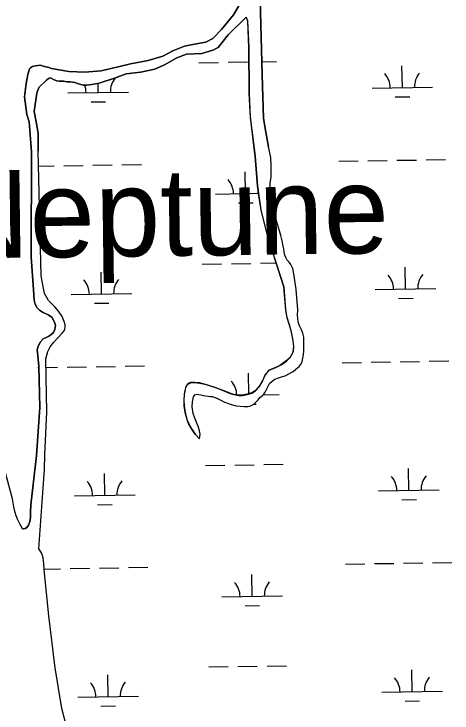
# Model space of a CAD drawing. Extents: x 3855477 to 3893699, y 299188 to 325115.
# Drawn here: x 3861611 to 3862334, y 317862 to 319017 of the extents above; entities that cross this region are included whole.
import ezdxf

# ---------------------------------------------------------------- set-up
doc = ezdxf.new("R2010")
doc.units = 0
for name, color, linetype in [('V-RIVR-EDGE', 7, 'Continuous'), ('V-TOPO-GNAM-IDEN', 7, 'Continuous'), ('V-TOPO-SHOR', 7, 'Continuous'), ('V-WETL-SWMP', 7, 'Continuous')]:
    doc.layers.add(name, color=color, linetype=linetype)

msp = doc.modelspace()

# ---------------------------------------------------------------- linework, layer by layer
at = {"layer": 'V-RIVR-EDGE'}
msp.add_spline([(3859519.3, 318133.3), (3859529.1, 318128.1), (3859557.8, 318117.3), (3859589.2, 318096.9), (3859608.3, 318091.7), (3859632.6, 318087.2), (3859655.7, 318083.2), (3859677.6, 318079.1), (3859695.1, 318076.3), (3859736.6, 318066.2), (3859764.5, 318061.4), (3859790.3, 318051.8), (3859824.2, 318038.5), (3859868.4, 318020.1), (3859890.7, 318012), (3859919.3, 318000.8), (3859946.4, 317985.2), (3859972.3, 317972.4), (3859987.4, 317966), (3859998.9, 317963.2), (3860007.3, 317958.4), (3860026.8, 317947.5), (3860045.9, 317937.5), (3860071.4, 317923.9), (3860094.9, 317913.9), (3860108.4, 317909.5), (3860130.3, 317897.1), (3860149.8, 317885.5), (3860170.5, 317876.3), (3860195.2, 317867.8), (3860221.1, 317854.2), (3860250.5, 317837.4), (3860275.2, 317822.6), (3860303, 317809.4), (3860359.6, 317779.3), (3860406.5, 317758.5), (3860436.8, 317744.1), (3860477.8, 317728.8), (3860496.5, 317723.6), (3860519.2, 317713.2), (3860555.8, 317696), (3860594.8, 317675.5), (3860632.3, 317656.3), (3860676.4, 317633.1), (3860726.6, 317605.5), (3860768, 317581.1), (3860790.7, 317570.6), (3860877.8, 317518.6), (3860907.7, 317504.6), (3860923.6, 317499.8), (3860947.5, 317491.7), (3860980.9, 317479.3), (3861011.2, 317471.3), (3861035.1, 317464.4), (3861065.4, 317456), (3861094, 317449.1), (3861112.8, 317445.1), (3861139.1, 317440.3), (3861167.3, 317430.2), (3861205.2, 317422.2), (3861236.2, 317418.9), (3861259.4, 317418), (3861273.7, 317417.2), (3861300, 317410), (3861325.9, 317397.5), (3861341.8, 317391.5), (3861353.7, 317387.9), (3861368.5, 317388.7), (3861377.7, 317388.7), (3861664.7, 317282.7), (3861681.1, 317276.7), (3861681.1, 317274.3), (3861687, 317270.7), (3861700.2, 317265.1), (3861705.7, 317256.7), (3861715.7, 317246.3), (3861721.2, 317241.5), (3861723.2, 317234.4), (3861726.4, 317227.6), (3861750.6, 317208), (3861757.4, 317197.6), (3861762.5, 317188.8), (3861767.3, 317187.2), (3861780.1, 317185.6), (3861788, 317178), (3861803.1, 317165.2), (3861810.3, 317151.6), (3861809.8, 317139.7), (3861814.2, 317132.9), (3861819.8, 317124.1), (3861817.3, 317108.6), (3861814.5, 317094.2), (3861799.4, 317086.7), (3861786.6, 317080.8), (3861777, 317076.8), (3861766.2, 317064.1), (3861761.8, 317062.9), (3861758.7, 317067.3), (3861753.9, 317083.2), (3861749.9, 317087.2), (3861742.8, 317089.6), (3861728.4, 317090.1), (3861720.1, 317091.3), (3861710.5, 317097.3), (3861701.4, 317107.7), (3861698.2, 317118), (3861695, 317124), (3861685.5, 317130.4), (3861670.3, 317131.3), (3861652.8, 317132.5), (3861648.4, 317134.1), (3861621.8, 317148.9), (3861610.2, 317154.5), (3861601.8, 317155.4), (3861592.3, 317158.2), (3861585.1, 317163.8), (3861576.8, 317171), (3861567.2, 317173.4), (3861541.3, 317180.2), (3861520.6, 317180.7), (3861509.8, 317179.9), (3861487.1, 317186.7), (3861457.3, 317196.8), (3861452.1, 317196), (3861445.3, 317191.2), (3861444.5, 317182.8), (3861448.1, 317178.4), (3861469.6, 317166.8), (3861511, 317148.8), (3861530.5, 317141.2), (3861552.8, 317132.4), (3861597, 317112.7)], degree=3, dxfattribs=at)
at = {"layer": 'V-TOPO-SHOR'}
msp.add_line((3861994.1, 319011.4), (3861994, 319011.8), dxfattribs=at)
for points in [[(3862017.2, 319041.4), (3862020.2, 318916.2), (3862022.4, 318844.4), (3862026.5, 318821.9), (3862030.6, 318797.3)], [(3861639.8, 318789.4), (3861635.9, 318838.7), (3861632.3, 318850.8), (3861628.3, 318880.1), (3861631, 318902.1), (3861633.7, 318916.7), (3861636.4, 318926.1), (3861637.9, 318927.7), (3861641.6, 318930.3), (3861646.3, 318931.3), (3861650, 318931.8), (3861654.2, 318932.3), (3861661, 318930.2), (3861668.3, 318928.6), (3861672.5, 318927), (3861701.3, 318921.6), (3861727.5, 318920.9), (3861754.7, 318922.9), (3861782.5, 318929.5), (3861803, 318934.7), (3861832.3, 318939.8), (3861856.4, 318947), (3861872.7, 318955.8), (3861892.1, 318963.5), (3861908.9, 318967.1), (3861927.3, 318970.1), (3861938.8, 318976.4), (3861953, 318991), (3861973.1, 319015.5), (3861982.1, 319030.1)], [(3861993.9, 319011.7), (3861964.5, 318982.5), (3861947.7, 318961.7), (3861938.7, 318957), (3861920.9, 318951.8), (3861895.7, 318950.4), (3861879.5, 318944.2), (3861859, 318932.8), (3861843.2, 318925.6), (3861819.6, 318921), (3861796.1, 318918), (3861776.6, 318910.7), (3861751.5, 318902.5), (3861739.4, 318900.5), (3861731, 318899.5), (3861725.8, 318899.5), (3861721.1, 318900.6), (3861715.8, 318902.2), (3861711.1, 318903.7), (3861703.3, 318904.8), (3861698.1, 318904.9), (3861693.3, 318905.9), (3861689.2, 318906), (3861685.5, 318906), (3861681.8, 318906.5), (3861677.1, 318908.1), (3861670.9, 318911.3), (3861667.7, 318910.3), (3861664.5, 318907.7), (3861651.9, 318895.2), (3861648.7, 318886.3), (3861644.4, 318855.9), (3861647.4, 318838.6), (3861650.5, 318819.8), (3861650.8, 318790.4)], [(3862009, 318781.7), (3862001, 318846.1), (3861999.1, 318885.9), (3861998.4, 318960.9), (3861996.6, 319005.4), (3861994.1, 319011.4)], [(3861909.7, 318322.9), (3861917.1, 318315.2), (3861917.9, 318323), (3861916.9, 318328.6), (3861914.6, 318336.2), (3861912.4, 318341.3), (3861909, 318349.1), (3861906.5, 318356.9), (3861905.1, 318367.8), (3861905.5, 318376.5), (3861907.3, 318384.7), (3861909.4, 318387.7), (3861912.9, 318388.8), (3861915.6, 318388.6), (3861918.9, 318388.1), (3861923.2, 318386.9), (3861931.4, 318385.6), (3861934.6, 318385.2), (3861938, 318384.9), (3861942.2, 318383.4), (3861946.8, 318381.6), (3861950.9, 318379.5), (3861954.6, 318377.7), (3861958.3, 318375.9), (3861962.3, 318374.5), (3861967.5, 318372.7), (3861977.5, 318369.5), (3861990.2, 318368.8), (3861992.9, 318368.6), (3861996.5, 318368.4), (3861999.6, 318369), (3862002.9, 318370.1), (3862006.4, 318372.3), (3862010.1, 318375.6), (3862013.7, 318379.8), (3862016.7, 318383.3), (3862020.6, 318386.4), (3862023.3, 318388.9), (3862025.5, 318392.1), (3862027.5, 318396.5), (3862032.7, 318406.6), (3862036.8, 318410.4), (3862041.2, 318414), (3862047.5, 318416), (3862052.3, 318417.5), (3862058.4, 318419.5), (3862071.5, 318426.4), (3862076, 318430.5), (3862081.4, 318434.9), (3862084.5, 318439), (3862086.2, 318443.2), (3862087.4, 318448.3), (3862088.6, 318454.3), (3862089, 318460.2), (3862089.4, 318467.2), (3862089.3, 318475.9), (3862088.9, 318483.1), (3862087.4, 318489.7), (3862085.2, 318495.5), (3862082.2, 318501.6), (3862079.6, 318508.4), (3862078.6, 318519.4), (3862079, 318528.3), (3862076.7, 318561.8), (3862073.3, 318584.4), (3862070.8, 318596.5), (3862067.7, 318603.3), (3862064.9, 318607), (3862061.6, 318610.2), (3862059.3, 318614.9), (3862057.6, 318618.5), (3862056.5, 318623.3), (3862056.4, 318629.2), (3862055.3, 318633.6), (3862053.5, 318642.4), (3862051.4, 318650.8), (3862049.2, 318658.6), (3862038.6, 318693.4), (3862034.3, 318718), (3862033.5, 318736.8), (3862035.1, 318747.7), (3862035.3, 318756.5), (3862035.3, 318766), (3862034.8, 318779.8), (3862030.6, 318797.3)], [(3861625, 318166.7), (3861626.5, 318166.4), (3861629.2, 318167.2), (3861631.9, 318169), (3861634.8, 318172.8), (3861636.8, 318178.7), (3861637.9, 318184.7), (3861638.3, 318193.6), (3861638.9, 318206.4), (3861648.1, 318287.9), (3861653.5, 318366.9), (3861651.7, 318435.4), (3861650.1, 318452.4), (3861649.3, 318462.4), (3861650.9, 318468), (3861654.6, 318475.6), (3861659.1, 318480.1), (3861663.9, 318482.8), (3861668.1, 318484.6), (3861671.9, 318487.1), (3861674.8, 318489.6), (3861676.6, 318492.2), (3861678.4, 318495.8), (3861679.2, 318502.5), (3861677.9, 318508), (3861673.2, 318516.3), (3861667.3, 318520.2), (3861658, 318524.3), (3861653, 318527.7), (3861648.9, 318531.5), (3861645.6, 318537.7), (3861644.1, 318544.4), (3861643.1, 318561.3), (3861639.3, 318615.6), (3861639.8, 318789.4)], [(3861652.1, 318133.3), (3861661.4, 318264.7), (3861661.6, 318289.2), (3861665.2, 318359.5), (3861663.4, 318447.5), (3861666.7, 318459.2), (3861670.4, 318467.3), (3861676.7, 318475), (3861683.6, 318482.6), (3861690.2, 318489.5), (3861694.1, 318494.4), (3861695.2, 318499.1), (3861695.4, 318503.4), (3861693.9, 318509.1), (3861690.2, 318517.1), (3861684.4, 318526.1), (3861678.1, 318533.1), (3861672.5, 318538.7), (3861667.9, 318543.7), (3861661.3, 318555.5), (3861655.6, 318584.5), (3861650.8, 318790.4)], [(3861909.7, 318322.9), (3861904.4, 318331.1), (3861898.9, 318340.7), (3861896.4, 318347), (3861894, 318356.4), (3861892.8, 318362.3), (3861891.9, 318369.6), (3861891.5, 318379), (3861892.1, 318388.2), (3861892.8, 318393), (3861894.3, 318399.6), (3861896.7, 318404.5), (3861899.1, 318406.7), (3861902.9, 318407.8), (3861909.6, 318408.2), (3861917.5, 318407.3), (3861925.6, 318405.3), (3861934.3, 318402.7), (3861943.2, 318399.8), (3861950.3, 318397.1), (3861960.7, 318393.1), (3861967.4, 318390.3), (3861973.7, 318388.5), (3861981.6, 318386.8), (3861987.8, 318386.9), (3861996.1, 318388.7), (3862003.3, 318390.7), (3862009.2, 318394.5), (3862015.8, 318401.7), (3862021.1, 318410.9), (3862025.7, 318421), (3862031.9, 318428.4), (3862039, 318431.3), (3862045.3, 318434), (3862051.6, 318437.4), (3862060.4, 318443.7), (3862066.8, 318449.6), (3862071.8, 318458.5), (3862072.4, 318468.1), (3862070.9, 318480.4), (3862068, 318493.6), (3862064.7, 318504.9), (3862061.4, 318515.4), (3862059.2, 318527.8), (3862056.4, 318566.1), (3862029.6, 318649), (3862018.6, 318693.1), (3862014.6, 318720.3), (3862012.9, 318732.9), (3862009, 318781.7)], [(3861625, 318166.7), (3861620.8, 318173.6), (3861616.7, 318182.7), (3861614.4, 318188), (3861612.6, 318193.7), (3861610.8, 318202.7), (3861608.6, 318215.9), (3861596.7, 318259.3)], [(3861668.1, 318022.9), (3861660.4, 318098.6), (3861660, 318109.2), (3861659.6, 318113.9), (3861659, 318118.6), (3861658.1, 318122.8), (3861656.1, 318127.2), (3861652.1, 318133.3)], [(3861690, 317870.1), (3861678.8, 317937), (3861668.1, 318022.9)], [(3861695.6, 317846.6), (3861690, 317870.1)]]:
    msp.add_lwpolyline(points, dxfattribs=at)
at = {"layer": 'V-WETL-SWMP'}
for p, q in [((3861916.1, 318936.4), (3861948.1, 318936.9)), ((3861964.1, 318937.1), (3861996.1, 318937.7)), ((3862019.7, 318938), (3862044.1, 318938.4)), ((3861749.3, 318922.5), (3861749.3, 318923.2)), ((3862251.7, 318895.4), (3862251.1, 318931.4)), ((3861749.8, 318887.2), (3861749.6, 318902.2)), ((3861699.9, 318886.4), (3861799.8, 318888)), ((3862201.7, 318894.6), (3862301.7, 318896.2)), ((3862239.9, 318879.8), (3862263.9, 318880.2)), ((3861738.1, 318871.6), (3861762.1, 318872)), ((3862146.8, 318773.6), (3862178.8, 318774.1)), ((3862194.8, 318774.4), (3862226.8, 318774.9)), ((3862242.8, 318775.2), (3862274.8, 318775.7)), ((3862290.8, 318775.9), (3862322.8, 318776.5)), ((3861651.4, 318765.5), (3861677, 318765.9)), ((3861693, 318766.2), (3861725, 318766.7)), ((3861741, 318767), (3861773, 318767.5)), ((3861789, 318767.8), (3861821, 318768.3)), ((3861993.1, 318720.3), (3861992.5, 318756.3)), ((3861943.1, 318719.5), (3862014.4, 318720.7)), ((3862034.2, 318721), (3862043.1, 318721.2)), ((3861981.3, 318704.7), (3862005.3, 318705.1)), ((3861921.6, 318603.7), (3861953.5, 318604.2)), ((3861969.5, 318604.5), (3862001.5, 318605)), ((3862017.5, 318605.3), (3862043.5, 318605.7)), ((3862257.1, 318562.8), (3862256.5, 318598.8)), ((3861755.3, 318554.6), (3861754.7, 318590.6)), ((3861705.3, 318553.8), (3861805.3, 318555.4)), ((3862207.1, 318561.9), (3862307.1, 318563.6)), ((3862245.4, 318547.1), (3862269.4, 318547.5)), ((3861743.5, 318539), (3861767.5, 318539.3)), ((3862152.2, 318441), (3862184.2, 318441.5)), ((3862200.2, 318441.7), (3862232.2, 318442.3)), ((3862248.2, 318442.5), (3862280.2, 318443)), ((3862296.2, 318443.3), (3862328.2, 318443.8)), ((3861650.4, 318432.8), (3861651.8, 318432.8)), ((3861663.7, 318433), (3861682.4, 318433.3)), ((3861698.4, 318433.6), (3861730.4, 318434.1)), ((3861746.4, 318434.3), (3861778.4, 318434.9)), ((3861794.4, 318435.1), (3861826.4, 318435.7)), ((3861998.5, 318389.7), (3861997.9, 318423.7)), ((3861979.9, 318387.4), (3861989.4, 318387.6)), ((3862022.4, 318388.1), (3862048.5, 318388.5)), ((3862006.6, 318372.4), (3862010.7, 318372.5)), ((3861927, 318271.1), (3861959, 318271.6)), ((3861975, 318271.9), (3862007, 318272.4)), ((3862023, 318272.7), (3862055, 318273.2)), ((3862262.5, 318230.1), (3862261.9, 318266.1)), ((3861760.7, 318221.9), (3861760.1, 318257.9)), ((3862212.5, 318229.3), (3862312.5, 318230.9)), ((3861710.7, 318221.1), (3861810.7, 318222.8)), ((3861748.9, 318206.3), (3861772.9, 318206.7)), ((3862250.8, 318214.5), (3862274.8, 318214.9)), ((3861799.8, 318102.5), (3861831.8, 318103)), ((3862157.7, 318108.3), (3862189.7, 318108.9)), ((3862205.6, 318109.1), (3862237.6, 318109.6)), ((3862253.6, 318109.9), (3862285.6, 318110.4)), ((3862301.6, 318110.7), (3862333.6, 318111.2)), ((3861660.3, 318100.2), (3861687.8, 318100.7)), ((3861703.8, 318100.9), (3861735.8, 318101.5)), ((3861751.8, 318101.7), (3861783.8, 318102.2)), ((3862003.9, 318055.1), (3862003.3, 318091.1)), ((3861953.9, 318054.3), (3862053.9, 318055.9)), ((3861992.2, 318039.5), (3862016.2, 318039.8)), ((3861932.4, 317938.5), (3861964.4, 317939)), ((3861980.4, 317939.2), (3862012.4, 317939.8)), ((3862028.4, 317940), (3862060.4, 317940.5)), ((3862267.9, 317897.5), (3862267.4, 317933.5)), ((3861766.1, 317889.3), (3861765.5, 317925.3)), ((3862218, 317896.7), (3862317.9, 317898.3)), ((3861716.1, 317888.5), (3861816.1, 317890.1)), ((3861754.4, 317873.7), (3861778.4, 317874.1)), ((3862256.2, 317881.9), (3862280.2, 317882.3))]:
    msp.add_line(p, q, dxfattribs=at)
for points in [[(3862027.5, 318396.5), (3862032.7, 318406.6), (3862036.8, 318410.4), (3862041.2, 318414), (3862047.5, 318416), (3862052.3, 318417.5), (3862058.4, 318419.5), (3862071.5, 318426.4), (3862076, 318430.5), (3862081.4, 318434.9), (3862084.5, 318439), (3862086.2, 318443.2), (3862087.4, 318448.3), (3862088.6, 318454.3), (3862089, 318460.2), (3862089.4, 318467.2), (3862089.3, 318475.9), (3862088.9, 318483.1), (3862087.4, 318489.7), (3862085.2, 318495.5), (3862082.2, 318501.6), (3862079.6, 318508.4), (3862078.6, 318519.4), (3862079, 318528.3), (3862076.7, 318561.8), (3862073.3, 318584.4), (3862070.8, 318596.5), (3862067.7, 318603.3), (3862064.9, 318607), (3862061.6, 318610.2), (3862059.3, 318614.9), (3862057.6, 318618.5), (3862056.5, 318623.3), (3862056.4, 318629.2), (3862055.3, 318633.6), (3862053.5, 318642.4), (3862051.4, 318650.8), (3862049.2, 318658.6), (3862038.6, 318693.4), (3862034.3, 318718), (3862033.5, 318736.8), (3862035.1, 318747.7), (3862035.3, 318756.5), (3862035.3, 318766), (3862034.8, 318779.8), (3862030.6, 318797.3), (3862026.5, 318821.9), (3862022.4, 318844.4), (3862020.2, 318916.2), (3862017.2, 319041.4)], [(3861982.1, 319030.1), (3861973.1, 319015.5), (3861953, 318991), (3861938.8, 318976.4), (3861927.3, 318970.1), (3861908.9, 318967.1), (3861892.1, 318963.5), (3861872.7, 318955.8), (3861856.4, 318947), (3861832.3, 318939.8), (3861803, 318934.7), (3861782.5, 318929.5), (3861754.7, 318922.9), (3861727.5, 318920.9)], [(3861859, 318932.8), (3861879.5, 318944.2), (3861895.7, 318950.4), (3861920.9, 318951.8), (3861938.7, 318957), (3861947.7, 318961.7), (3861964.5, 318982.5), (3861993.9, 319011.7), (3861996.4, 319005.6), (3861998.3, 318961.1), (3861998.9, 318886.2), (3862000.8, 318846.4), (3862008.8, 318781.9), (3862012.7, 318733.1), (3862014.4, 318720.6), (3862018.4, 318693.4), (3862029.4, 318649.3), (3862056.2, 318566.4), (3862059, 318528.1), (3862061.2, 318515.7), (3862064.5, 318505.2), (3862067.8, 318493.9), (3862070.7, 318480.6), (3862072.2, 318468.4), (3862071.6, 318458.7), (3862066.6, 318449.9), (3862060.2, 318443.9), (3862051.4, 318437.6), (3862045.1, 318434.2), (3862038.8, 318431.6), (3862031.7, 318428.6), (3862025.5, 318421.2), (3862020.9, 318411.1), (3862015.6, 318402), (3862009, 318394.7), (3862003.1, 318391), (3861995.9, 318389), (3861987.6, 318387.2), (3861981.4, 318387.1), (3861973.5, 318388.7), (3861967.2, 318390.6), (3861960.6, 318393.3), (3861950.1, 318397.4), (3861943, 318400), (3861934.1, 318403), (3861925.4, 318405.6), (3861917.3, 318407.6), (3861909.4, 318408.5), (3861902.7, 318408.1), (3861898.9, 318407), (3861896.5, 318404.8), (3861894.1, 318399.9), (3861892.6, 318393.2), (3861891.9, 318388.5), (3861891.3, 318379.3), (3861891.7, 318369.9), (3861892.6, 318362.6), (3861893.8, 318356.7), (3861896.2, 318347.3), (3861898.7, 318340.9), (3861904.2, 318331.3), (3861909.7, 318322.9), (3861917.1, 318315.2), (3861917.9, 318323), (3861916.9, 318328.6), (3861914.6, 318336.2), (3861912.4, 318341.3), (3861909, 318349.1), (3861906.5, 318356.9), (3861905.1, 318367.8), (3861905.5, 318376.5), (3861907.3, 318384.7), (3861909.4, 318387.7), (3861912.9, 318388.8), (3861915.6, 318388.6), (3861918.9, 318388.1), (3861923.2, 318386.9), (3861931.4, 318385.6), (3861934.6, 318385.2), (3861938, 318384.9), (3861942.2, 318383.4), (3861946.8, 318381.6), (3861950.9, 318379.5), (3861954.6, 318377.7), (3861958.3, 318375.9), (3861962.3, 318374.5), (3861967.5, 318372.7), (3861977.5, 318369.5), (3861990.2, 318368.8), (3861992.9, 318368.6), (3861996.5, 318368.4), (3861999.6, 318369), (3862002.9, 318370.1), (3862006.4, 318372.3), (3862010.1, 318375.6), (3862013.7, 318379.8), (3862016.7, 318383.3), (3862020.6, 318386.4), (3862023.3, 318388.9), (3862025.5, 318392.1), (3862027.5, 318396.5)], [(3861727.5, 318920.9), (3861701.3, 318921.6), (3861672.5, 318927), (3861668.3, 318928.6), (3861661, 318930.2), (3861654.2, 318932.3), (3861650, 318931.8), (3861646.3, 318931.3), (3861641.6, 318930.3), (3861637.9, 318927.7), (3861636.4, 318926.1), (3861633.7, 318916.7), (3861631, 318902.1), (3861628.3, 318880.1), (3861632.3, 318850.8), (3861635.9, 318838.7), (3861639.8, 318789.4), (3861639.3, 318615.6), (3861643.1, 318561.3), (3861644.1, 318544.4), (3861645.6, 318537.7), (3861648.9, 318531.5), (3861653, 318527.7), (3861658, 318524.3), (3861667.3, 318520.2), (3861673.2, 318516.3), (3861677.9, 318508), (3861679.2, 318502.5), (3861678.4, 318495.8), (3861676.6, 318492.2), (3861674.8, 318489.6), (3861671.9, 318487.1), (3861668.1, 318484.6), (3861663.9, 318482.8), (3861659.1, 318480.1), (3861654.6, 318475.6), (3861650.9, 318468), (3861649.3, 318462.4), (3861650.1, 318452.4), (3861651.7, 318435.4), (3861653.5, 318366.9), (3861648.1, 318287.9), (3861638.9, 318206.4), (3861638.3, 318193.6), (3861637.9, 318184.7), (3861636.8, 318178.7), (3861634.8, 318172.8), (3861631.9, 318169), (3861629.2, 318167.2), (3861626.5, 318166.4), (3861625, 318166.7), (3861620.8, 318173.6), (3861616.7, 318182.7), (3861614.4, 318188), (3861612.6, 318193.7), (3861610.8, 318202.7)], [(3861695.6, 317846.6), (3861690, 317870.1), (3861678.8, 317937), (3861668.1, 318022.9), (3861660.4, 318098.6), (3861660, 318109.2), (3861659.6, 318113.9), (3861659, 318118.6), (3861658.1, 318122.8), (3861656.1, 318127.2), (3861652.1, 318133.3), (3861661.4, 318264.7), (3861661.6, 318289.2), (3861665.2, 318359.5), (3861663.4, 318447.5), (3861666.7, 318459.2), (3861670.4, 318467.3), (3861676.7, 318475), (3861683.6, 318482.6), (3861690.2, 318489.5), (3861694.1, 318494.4), (3861695.2, 318499.1), (3861695.4, 318503.4), (3861693.9, 318509.1), (3861690.2, 318517.1), (3861684.4, 318526.1), (3861678.1, 318533.1), (3861672.5, 318538.7), (3861667.9, 318543.7), (3861661.4, 318555.5), (3861655.6, 318584.5), (3861650.8, 318790.4), (3861650.5, 318819.8), (3861647.4, 318838.6), (3861644.4, 318855.9), (3861648.7, 318886.3), (3861651.9, 318895.2), (3861664.5, 318907.7), (3861667.7, 318910.3), (3861670.9, 318911.3), (3861677.1, 318908.1), (3861681.8, 318906.5), (3861685.5, 318906), (3861689.2, 318906), (3861693.3, 318905.9), (3861698.1, 318904.9), (3861703.3, 318904.8), (3861711.1, 318903.7), (3861715.8, 318902.2), (3861721.1, 318900.6), (3861725.8, 318899.5), (3861731, 318899.5), (3861739.4, 318900.5), (3861751.5, 318902.5), (3861776.6, 318910.7), (3861796.1, 318918), (3861819.6, 318921), (3861843.2, 318925.6), (3861859, 318932.8)]]:
    msp.add_lwpolyline(points, dxfattribs=at)
for centre, start, end in [((3861805.1, 318888.6), 140.1615, 181.7052), ((3862196.4, 318895), 0.1615, 41.7052), ((3862306.9, 318896.8), 140.1615, 181.7052), ((3861694.6, 318886.8), 0.1615, 21.0975), ((3861937.8, 318719.9), 0.1615, 41.7052), ((3862048.3, 318721.7), 170.9864, 181.7052), ((3861700, 318554.2), 0.1615, 41.7052), ((3861810.5, 318556), 140.1615, 181.7052), ((3862201.9, 318562.3), 0.1615, 41.7052), ((3862312.3, 318564.1), 140.1615, 181.7052), ((3861943.2, 318387.3), 0.6798, 41.7052), ((3862207.3, 318229.7), 0.1615, 41.7052), ((3862317.8, 318231.5), 140.1615, 181.7052), ((3861705.4, 318221.5), 0.1615, 41.7052), ((3861815.9, 318223.3), 140.1615, 181.7052), ((3861948.7, 318054.7), 0.1615, 41.7052), ((3862059.1, 318056.4), 140.1615, 181.7052), ((3862212.7, 317897.1), 0.1615, 41.7052), ((3862323.2, 317898.9), 140.1615, 181.7052), ((3861710.9, 317888.9), 0.1615, 41.7052), ((3861821.3, 317890.7), 140.1615, 181.7052)]:
    msp.add_arc(centre, 35.2, start, end, dxfattribs=at)

# ---------------------------------------------------------------- texts
at = {"layer": 'V-TOPO-GNAM-IDEN'}
msp.add_text('Neptune', height=145, rotation=0.7186, dxfattribs=at).set_placement((3861497.3, 318612.8))

doc.saveas('drawing.dxf')
